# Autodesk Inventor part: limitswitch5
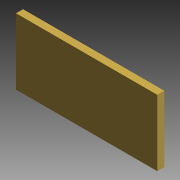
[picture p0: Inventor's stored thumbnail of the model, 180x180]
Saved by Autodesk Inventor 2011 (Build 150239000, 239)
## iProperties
Created: 2002-01
Part Number: limitswitch5
Document SubType Name: Modeling
Density: 1 g/cm^3
Control State: 0
Master: False
Checked Out: False
Shininess: 0.0
Density: 0.0
Volumn: 0.0
Area: 0.0
PropertySet Name: Model Information
Author: Administrator
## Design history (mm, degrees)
node "Base1"
body "Solid1"
